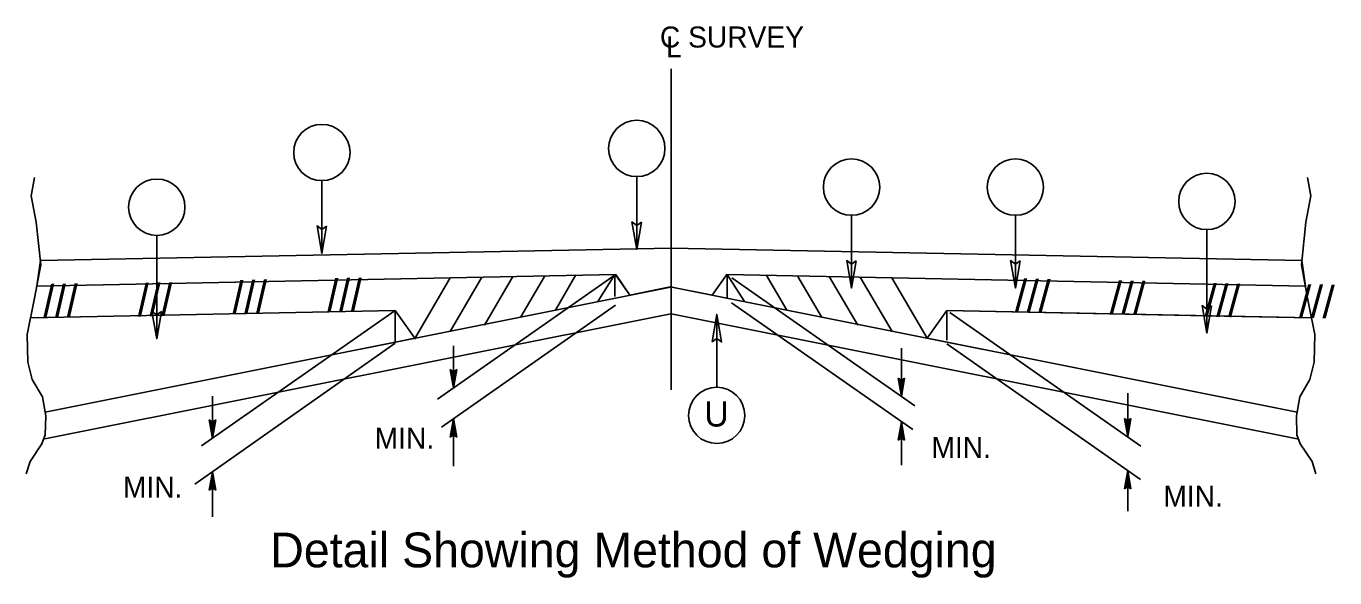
# Model space of a CAD drawing. Extents: x 1818040 to 1825768, y 638918 to 648046.
# Drawn here: x 1824454 to 1825128, y 638918 to 639202 of the extents above; entities that cross this region are included whole.
import ezdxf

# ---------------------------------------------------------------- set-up
doc = ezdxf.new("R2010")
doc.units = 0
for name, color, linetype in [('Typical Detail Wedge2 CELL', 7, 'Continuous'), ('Typical ID Circle CELL', 7, 'Continuous'), ('Typical Terminator CELL', 7, 'Continuous'), ('Typical Text Centerline CELL', 7, 'Continuous'), ('Typical Text General CELL', 7, 'Continuous'), ('Typical Text ID Circle CELL', 7, 'Continuous')]:
    doc.layers.add(name, color=color, linetype=linetype)

msp = doc.modelspace()

# ---------------------------------------------------------------- linework, layer by layer
at = {"layer": 'Typical Detail Wedge2 CELL'}
for p, q in [((1824786.42, 639014.82), (1824786.42, 639180.24)), ((1824786.42, 639014.82), (1824786.42, 639127.8)), ((1824786.41, 639087.9), (1824461.75, 639081.42)), ((1824461.75, 639081.42), (1824786.41, 639087.9)), ((1824786.41, 639087.9), (1825111.09, 639081.42)), ((1824786.44, 639087.9), (1825111.09, 639081.42)), ((1824459.9, 639068.37), (1824461.75, 639081.42)), ((1825111.09, 639081.42), (1825112.96, 639068.37)), ((1824757.93, 639074.33), (1824459.9, 639068.37)), ((1824757.93, 639074.33), (1824459.9, 639068.37)), ((1824757.56, 639074.09), (1824666.09, 639010.02)), ((1824748.7, 639060.45), (1824757.51, 639074.21)), ((1824757.51, 639074.21), (1824757.51, 639062.89)), ((1824765.22, 639063.63), (1824757.93, 639074.33)), ((1824815.14, 639074.33), (1824807.61, 639063.63)), ((1824815.14, 639074.33), (1824807.61, 639063.63)), ((1824814.66, 639074.09), (1824815.13, 639074.06)), ((1824815.14, 639074.33), (1825112.96, 639068.37)), ((1825112.96, 639068.37), (1824815.14, 639074.33)), ((1824824.14, 639060.45), (1824815.33, 639074.21)), ((1824815.33, 639074.21), (1824815.33, 639061.75)), ((1824786.9, 639067.94), (1824464.18, 639003.38)), ((1824672.78, 639072.62), (1824654.33, 639041)), ((1824688.98, 639072.95), (1824672.65, 639044.92)), ((1824705.02, 639073.26), (1824690.36, 639048.14)), ((1824721.18, 639073.23), (1824709.03, 639052.42)), ((1824737.47, 639074.06), (1824726.89, 639055.91)), ((1824757.93, 639073.98), (1824765.22, 639063.63)), ((1824785.93, 639067.94), (1824765.22, 639063.63)), ((1824785.93, 639067.94), (1825108.66, 639003.38)), ((1824807.61, 639063.63), (1824785.93, 639067.94)), ((1824817.62, 639072.6), (1824911.86, 639006.59)), ((1824835.36, 639074.06), (1824845.96, 639055.91)), ((1824851.65, 639073.23), (1824863.8, 639052.42)), ((1824867.81, 639073.26), (1824882.48, 639048.14)), ((1824883.85, 639072.95), (1824900.19, 639044.92)), ((1824900.07, 639072.62), (1824918.24, 639041.47)), ((1824644.39, 639055.78), (1824456.74, 639052.02)), ((1824456.74, 639052.02), (1824644.39, 639055.78)), ((1824786.29, 639054.05), (1824464.08, 638989.6)), ((1824644.39, 639055.78), (1824544.75, 638986)), ((1824654.59, 639041.43), (1824644.39, 639055.78)), ((1824644.39, 639055.78), (1824644.39, 639039.4)), ((1824644.39, 639055.78), (1824654.57, 639041.47)), ((1824757.78, 639058.43), (1824668.26, 638995.75)), ((1824786.54, 639054.05), (1825109.51, 638989.44)), ((1824817.49, 639059.77), (1824910.81, 638994.43)), ((1824928.44, 639055.78), (1824918.24, 639041.47)), ((1824918.26, 639041.47), (1824928.44, 639055.78)), ((1824928.44, 639055.78), (1825116.11, 639052.02)), ((1824928.44, 639055.78), (1824928.44, 639040.56)), ((1825062.28, 639053.09), (1824928.44, 639055.78)), ((1824929.96, 639054.72), (1825028.24, 638985.9)), ((1825116.11, 639052.02), (1825062.28, 639053.09)), ((1824654.57, 639041.47), (1824644.39, 639039.43)), ((1824918.24, 639041.47), (1824961.13, 639032.89)), ((1824644.3, 639038.89), (1824541.3, 638966.41)), ((1824644.39, 639039.43), (1824611.71, 639032.89)), ((1824674.42, 639037.62), (1824674.42, 639015.87)), ((1824904.98, 639036.37), (1824904.98, 639011.43)), ((1824928.44, 639038.58), (1825028.07, 638968.79)), ((1824611.71, 639032.89), (1824464.18, 639003.38)), ((1824961.13, 639032.89), (1825108.66, 639003.38)), ((1824674.42, 639015.87), (1824672.73, 639025.4)), ((1824674.42, 639024.16), (1824672.73, 639025.4)), ((1824674.42, 639015.87), (1824672.97, 639025.22)), ((1824673.21, 639025.04), (1824674.42, 639015.87)), ((1824674.42, 639015.87), (1824673.45, 639024.88)), ((1824673.7, 639024.7), (1824674.42, 639015.87)), ((1824674.42, 639015.87), (1824673.94, 639024.52)), ((1824674.18, 639024.34), (1824674.42, 639015.87)), ((1824674.42, 639015.87), (1824676.11, 639025.4)), ((1824676.11, 639025.4), (1824674.42, 639024.16)), ((1824675.87, 639025.22), (1824674.42, 639015.87)), ((1824674.42, 639015.87), (1824675.61, 639025.04)), ((1824675.37, 639024.88), (1824674.42, 639015.87)), ((1824674.42, 639015.87), (1824675.13, 639024.7)), ((1824674.89, 639024.52), (1824674.42, 639015.87)), ((1824674.42, 639015.87), (1824674.66, 639024.34)), ((1824674.42, 639024.16), (1824674.42, 639015.87)), ((1824904.98, 639011.43), (1824903.29, 639020.97)), ((1824904.98, 639019.73), (1824903.29, 639020.97)), ((1824904.98, 639011.43), (1824903.53, 639020.8)), ((1824903.77, 639020.62), (1824904.98, 639011.43)), ((1824904.98, 639011.43), (1824904.01, 639020.44)), ((1824904.25, 639020.26), (1824904.98, 639011.43)), ((1824904.98, 639011.43), (1824906.66, 639020.97)), ((1824906.66, 639020.97), (1824904.98, 639019.73)), ((1824906.41, 639020.8), (1824904.98, 639011.43)), ((1824904.98, 639011.43), (1824906.17, 639020.62)), ((1824905.93, 639020.44), (1824904.98, 639011.43)), ((1824904.98, 639011.43), (1824905.69, 639020.26)), ((1824904.98, 639011.43), (1824904.49, 639020.09)), ((1824904.73, 639019.91), (1824904.98, 639011.43)), ((1824905.45, 639020.09), (1824904.98, 639011.43)), ((1824904.98, 639011.43), (1824905.22, 639019.91)), ((1824904.98, 639019.73), (1824904.98, 639011.43)), ((1824550.36, 639011.62), (1824550.36, 638989.92)), ((1825021.48, 639013.19), (1825021.48, 638990.63)), ((1824674.42, 639000.06), (1824672.73, 638990.52)), ((1824672.97, 638990.71), (1824674.42, 639000.06)), ((1824674.42, 639000.06), (1824673.21, 638990.87)), ((1824673.45, 638991.06), (1824674.42, 639000.06)), ((1824674.42, 639000.06), (1824673.7, 638991.23)), ((1824673.94, 638991.4), (1824674.42, 639000.06)), ((1824674.42, 639000.06), (1824674.18, 638991.58)), ((1824674.42, 639000.06), (1824674.42, 638975.56)), ((1824674.42, 639000.06), (1824676.11, 638990.52)), ((1824674.42, 638991.76), (1824674.42, 639000.06)), ((1824674.66, 638991.58), (1824674.42, 639000.06)), ((1824674.42, 639000.06), (1824674.89, 638991.4)), ((1824675.13, 638991.23), (1824674.42, 639000.06)), ((1824674.42, 639000.06), (1824675.37, 638991.06)), ((1824675.61, 638990.87), (1824674.42, 639000.06)), ((1824674.42, 639000.06), (1824675.87, 638990.71)), ((1825021.48, 638990.63), (1825019.8, 639000.17)), ((1825021.48, 638998.94), (1825019.8, 639000.17)), ((1825021.48, 638990.63), (1825020.04, 638999.99)), ((1825021.48, 638990.63), (1825023.16, 639000.17)), ((1825023.16, 639000.17), (1825021.48, 638998.94)), ((1825022.91, 638999.99), (1825021.48, 638990.63)), ((1824550.36, 638989.92), (1824548.66, 638999.47)), ((1824550.36, 638998.24), (1824548.66, 638999.47)), ((1824550.36, 638989.92), (1824548.9, 638999.3)), ((1824549.17, 638999.11), (1824550.36, 638989.92)), ((1824550.36, 638989.92), (1824549.4, 638998.94)), ((1824549.64, 638998.77), (1824550.36, 638989.92)), ((1824550.36, 638989.92), (1824549.88, 638998.6)), ((1824550.12, 638998.42), (1824550.36, 638989.92)), ((1824550.36, 638989.92), (1824552.04, 638999.47)), ((1824552.04, 638999.47), (1824550.36, 638998.24)), ((1824551.8, 638999.3), (1824550.36, 638989.92)), ((1824550.36, 638989.92), (1824551.56, 638999.11)), ((1824551.33, 638998.94), (1824550.36, 638989.92)), ((1824550.36, 638989.92), (1824551.08, 638998.77)), ((1824550.85, 638998.6), (1824550.36, 638989.92)), ((1824550.36, 638989.92), (1824550.6, 638998.42)), ((1824550.36, 638998.24), (1824550.36, 638989.92)), ((1824904.98, 638998.51), (1824903.29, 638988.96)), ((1824903.53, 638989.15), (1824904.98, 638998.51)), ((1824904.98, 638998.51), (1824903.77, 638989.32)), ((1824904.01, 638989.51), (1824904.98, 638998.51)), ((1824904.98, 638998.51), (1824904.25, 638989.68)), ((1824904.49, 638989.85), (1824904.98, 638998.51)), ((1824904.98, 638998.51), (1824904.73, 638990.03)), ((1824904.98, 638998.51), (1824904.98, 638976.19)), ((1824904.98, 638998.51), (1824906.66, 638988.96)), ((1824904.98, 638990.2), (1824904.98, 638998.51)), ((1824905.22, 638990.03), (1824904.98, 638998.51)), ((1824904.98, 638998.51), (1824905.45, 638989.85)), ((1824905.69, 638989.68), (1824904.98, 638998.51)), ((1824904.98, 638998.51), (1824905.93, 638989.51)), ((1824906.17, 638989.32), (1824904.98, 638998.51)), ((1824904.98, 638998.51), (1824906.41, 638989.15)), ((1825020.28, 638999.82), (1825021.48, 638990.63)), ((1825021.48, 638990.63), (1825020.51, 638999.66)), ((1825020.75, 638999.47), (1825021.48, 638990.63)), ((1825021.48, 638990.63), (1825020.99, 638999.3)), ((1825021.23, 638999.11), (1825021.48, 638990.63)), ((1825021.48, 638990.63), (1825022.67, 638999.82)), ((1825022.44, 638999.66), (1825021.48, 638990.63)), ((1825021.48, 638990.63), (1825022.2, 638999.47)), ((1825021.96, 638999.3), (1825021.48, 638990.63)), ((1825021.48, 638990.63), (1825021.72, 638999.11)), ((1825021.48, 638998.94), (1825021.48, 638990.63)), ((1824672.73, 638990.52), (1824674.42, 638991.76)), ((1824674.42, 638991.76), (1824676.11, 638990.52)), ((1824903.29, 638988.96), (1824904.98, 638990.2)), ((1824904.98, 638990.2), (1824906.66, 638988.96)), ((1825021.48, 638973.42), (1825019.8, 638963.87)), ((1825020.04, 638964.05), (1825021.48, 638973.42)), ((1825021.48, 638973.42), (1825020.28, 638964.23)), ((1825020.51, 638964.41), (1825021.48, 638973.42)), ((1825021.48, 638973.42), (1825020.75, 638964.59)), ((1825020.99, 638964.77), (1825021.48, 638973.42)), ((1825021.48, 638973.42), (1825021.23, 638964.94)), ((1825021.48, 638973.42), (1825021.48, 638952.46)), ((1825021.48, 638973.42), (1825023.16, 638963.87)), ((1825021.48, 638965.13), (1825021.48, 638973.42)), ((1825021.72, 638964.94), (1825021.48, 638973.42)), ((1825021.48, 638973.42), (1825021.96, 638964.77)), ((1825022.2, 638964.59), (1825021.48, 638973.42)), ((1825021.48, 638973.42), (1825022.44, 638964.41)), ((1825022.67, 638964.23), (1825021.48, 638973.42)), ((1825021.48, 638973.42), (1825022.91, 638964.05)), ((1824550.36, 638972.75), (1824548.66, 638963.21)), ((1824548.93, 638963.39), (1824550.36, 638972.75)), ((1824550.36, 638972.75), (1824549.17, 638963.56)), ((1824549.4, 638963.74), (1824550.36, 638972.75)), ((1824550.36, 638972.75), (1824549.64, 638963.92)), ((1824549.88, 638964.09), (1824550.36, 638972.75)), ((1824550.36, 638972.75), (1824550.12, 638964.26)), ((1824550.36, 638972.75), (1824550.36, 638949.55)), ((1824550.36, 638972.75), (1824552.04, 638963.21)), ((1824550.36, 638964.45), (1824550.36, 638972.75)), ((1824550.6, 638964.26), (1824550.36, 638972.75)), ((1824550.36, 638972.75), (1824550.85, 638964.09)), ((1824551.09, 638963.92), (1824550.36, 638972.75)), ((1824550.36, 638972.75), (1824551.33, 638963.74)), ((1824551.56, 638963.56), (1824550.36, 638972.75)), ((1824550.36, 638972.75), (1824551.8, 638963.39)), ((1824548.66, 638963.21), (1824550.36, 638964.45)), ((1824550.36, 638964.45), (1824552.04, 638963.21)), ((1825019.8, 638963.87), (1825021.48, 638965.13)), ((1825021.48, 638965.13), (1825023.16, 638963.87))]:
    msp.add_line(p, q, dxfattribs=at)
for points in [[(1824458.73, 639124.27), (1824457, 639114.75), (1824459.6, 639101.23), (1824461.89, 639079.34), (1824458.73, 639062.06), (1824454.99, 639043.34), (1824455.28, 639029.22), (1824457.58, 639020.31), (1824462.78, 639011.37), (1824464.49, 639001.58), (1824464.21, 638991.79), (1824462.48, 638987.17), (1824456.44, 638977.96), (1824454.42, 638971.62)], [(1825114.1, 639124.27), (1825115.83, 639114.75), (1825113.24, 639101.23), (1825110.94, 639079.34), (1825114.1, 639062.06), (1825117.85, 639043.34), (1825117.56, 639029.22), (1825115.25, 639020.31), (1825110.07, 639011.37), (1825108.35, 639001.58), (1825108.62, 638991.79), (1825110.35, 638987.17), (1825116.39, 638977.96), (1825118.41, 638971.62)], [(1824464.17, 639003.38), (1824462.78, 639011.37), (1824457.58, 639020.31), (1824455.28, 639029.22), (1824454.99, 639043.34), (1824456.72, 639052.02)], [(1825108.66, 639003.38), (1825110.07, 639011.37), (1825115.25, 639020.31), (1825117.56, 639029.22), (1825117.85, 639043.34), (1825116.11, 639052.02)]]:
    msp.add_lwpolyline(points, dxfattribs=at)
at = {"layer": 'Typical ID Circle CELL'}
for p, q in [((1824606.65, 639122.62), (1824606.65, 639085.14)), ((1824768.79, 639124.71), (1824768.79, 639087.23)), ((1824879.33, 639104.79), (1824879.33, 639067.31)), ((1824963.68, 639104.79), (1824963.68, 639067.31)), ((1824521.65, 639094.46), (1824521.65, 639041.17)), ((1825062.28, 639097.43), (1825062.28, 639044.14)), ((1824809.91, 639016.25), (1824809.91, 639053.73))]:
    msp.add_line(p, q, dxfattribs=at)
for centre in [(1824606.65, 639137.12), (1824768.79, 639139.21), (1824879.33, 639119.28), (1824963.67, 639119.28), (1824521.65, 639108.96), (1825062.27, 639111.93), (1824809.91, 639001.75)]:
    msp.add_circle(centre, 14.5, dxfattribs=at)
at = {"layer": 'Typical Terminator CELL'}
for points in [[(1824771.21, 639101.29), (1824768.79, 639087.23), (1824766.29, 639101.37), (1824768.79, 639099.57)], [(1824771.21, 639101.29), (1824768.79, 639087.23), (1824766.29, 639101.37), (1824768.79, 639099.57)], [(1824609.07, 639099.2), (1824606.65, 639085.14), (1824604.15, 639099.28), (1824606.65, 639097.48)], [(1824609.07, 639099.2), (1824606.65, 639085.14), (1824604.15, 639099.28), (1824606.65, 639097.48)], [(1824881.75, 639081.37), (1824879.33, 639067.31), (1824876.83, 639081.45), (1824879.33, 639079.65)], [(1824881.75, 639081.37), (1824879.33, 639067.31), (1824876.83, 639081.45), (1824879.33, 639079.65)], [(1824966.1, 639081.37), (1824963.68, 639067.31), (1824961.18, 639081.45), (1824963.68, 639079.65)], [(1824966.1, 639081.37), (1824963.68, 639067.31), (1824961.18, 639081.45), (1824963.68, 639079.65)], [(1824524.08, 639055.23), (1824521.65, 639041.17), (1824519.15, 639055.31), (1824521.65, 639053.51)], [(1824524.08, 639055.23), (1824521.65, 639041.17), (1824519.15, 639055.31), (1824521.65, 639053.51)], [(1825064.7, 639058.2), (1825062.28, 639044.14), (1825059.78, 639058.28), (1825062.28, 639056.48)], [(1824807.49, 639039.67), (1824809.91, 639053.73), (1824812.41, 639039.59), (1824809.91, 639041.38)], [(1824807.49, 639039.67), (1824809.91, 639053.73), (1824812.41, 639039.59), (1824809.91, 639041.38)]]:
    msp.add_lwpolyline(points, close=True, dxfattribs=at)

# ---------------------------------------------------------------- texts
at = {"layer": 'Typical Detail Wedge2 CELL'}
for height, rotation, p in [(16.281, 1.14473, (1824463.19, 639052.25)), (16.281, 1.14639, (1824511.85, 639052.82)), (16.275, 1.14453, (1824560.62, 639054.25)), (16.276, 1.14629, (1824609.44, 639055.25)), (16.276, 358.85527, (1824963.4, 639055.25)), (16.275, 358.85361, (1825012.22, 639054.25)), (16.281, 358.85537, (1825060.98, 639052.82)), (16.281, 358.85371, (1825109.64, 639052.25))]:
    msp.add_text('/// ', height=height, rotation=rotation, dxfattribs=at).set_placement(p)
for p in [(1824633.81, 638984.56), (1824920.47, 638979.84), (1824504.23, 638959.41), (1825039.85, 638954.7)]:
    msp.add_text('MIN.', height=10.846, dxfattribs=at).set_placement(p)
at = {"layer": 'Typical Text Centerline CELL'}
for s, height, p in [('C SURVEY ', 10.846, (1824780.68, 639191.16)), ('L', 10.85, (1824783.85, 639186.09))]:
    msp.add_text(s, height=height, dxfattribs=at).set_placement(p)
at = {"layer": 'Typical Text General CELL'}
msp.add_text('Detail Showing Method of Wedging', height=17.9034, dxfattribs=at).set_placement((1824580.07, 638923.5))
at = {"layer": 'Typical Text ID Circle CELL'}
msp.add_text('U', height=12.98, dxfattribs=at).set_placement((1824803.57, 638996.01))

doc.saveas('drawing.dxf')
